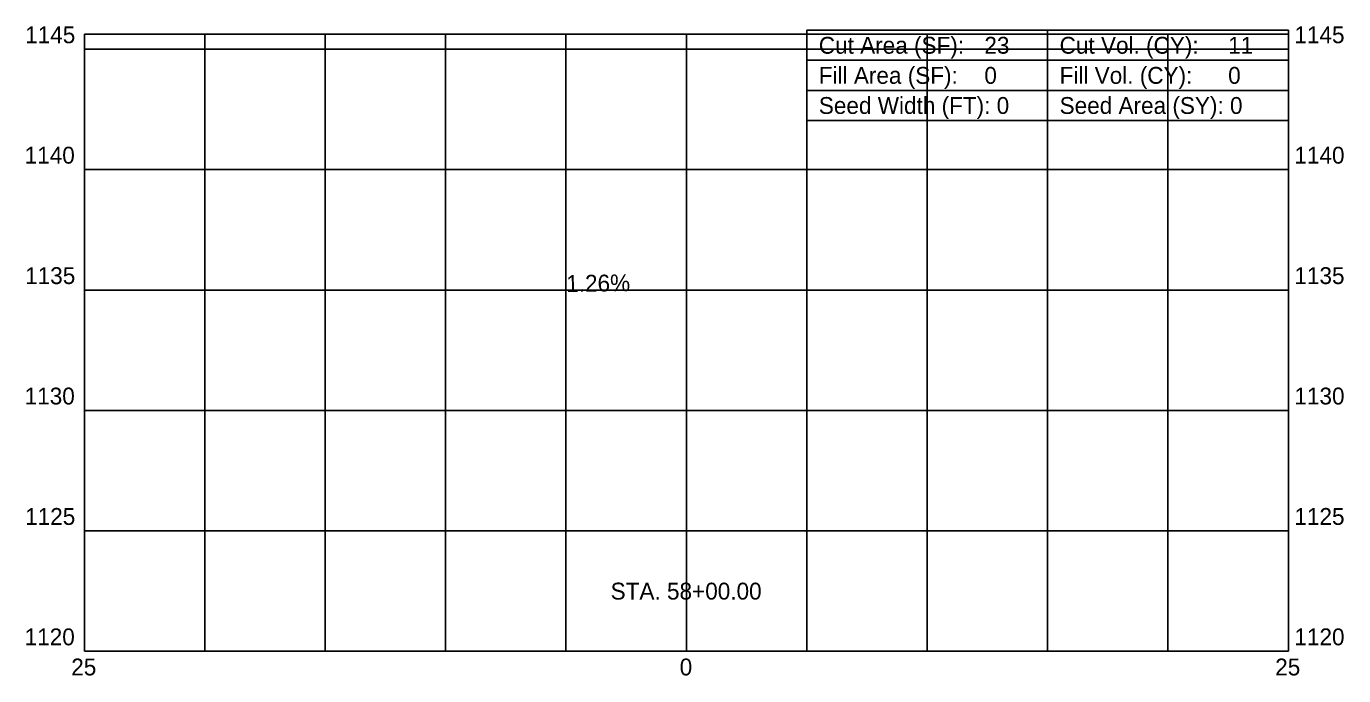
# Model space of a CAD drawing. Extents: x -27.4 to 27.3, y 1119 to 1146.
import ezdxf

# ---------------------------------------------------------------- set-up
doc = ezdxf.new("R2010")
doc.units = 0
for name, color, linetype in [('Default', 7, 'Continuous'), ('SH_Data', 7, 'Continuous'), ('SH_Major_Grid_Line', 7, 'Continuous'), ('SH_Masking', 7, 'Continuous'), ('SH_Text', 7, 'Continuous')]:
    doc.layers.add(name, color=color, linetype=linetype)

msp = doc.modelspace()

# ---------------------------------------------------------------- linework, layer by layer
at = {"layer": 'Default'}
msp.add_circle((25, 1145.789), 0.000417, dxfattribs=at)
msp.add_circle((25, 1145.789), 0.000417, dxfattribs=at)
msp.add_circle((25, 1145.789), 0.000417, dxfattribs=at)
msp.add_circle((25, 1145.789), 0.000417, dxfattribs=at)
msp.add_circle((25, 1145.789), 0.000417, dxfattribs=at)
msp.add_circle((25, 1145.789), 0.000417, dxfattribs=at)
msp.add_circle((25, 1145.789), 0.000417, dxfattribs=at)
msp.add_circle((25, 1145.789), 0.000417, dxfattribs=at)
msp.add_circle((25, 1145.789), 0.000417, dxfattribs=at)
msp.add_circle((25, 1145.789), 0.000417, dxfattribs=at)
msp.add_circle((25, 1145.789), 0.000417, dxfattribs=at)
msp.add_circle((25, 1145.789), 0.000417, dxfattribs=at)
at = {"layer": 'SH_Data'}
for p, q in [((5, 1145.789), (25, 1145.789)), ((5, 1145.789), (5, 1143.289)), ((15, 1145.789), (15, 1142.039)), ((25, 1145.789), (25, 1143.289)), ((5, 1144.539), (25, 1144.539)), ((5, 1143.289), (25, 1143.289)), ((13.298, 1142.664), (13.298, 1142.664)), ((22.946, 1142.664), (22.946, 1142.664))]:
    msp.add_line(p, q, dxfattribs=at)
msp.add_lwpolyline([(5, 1143.289), (5, 1142.039), (25, 1142.039), (25, 1143.289)], dxfattribs=at)
at = {"layer": 'SH_Major_Grid_Line'}
for p, q in [((-25, 1145.626), (25, 1145.626)), ((-25, 1120), (-25, 1145.626)), ((-20, 1120), (-20, 1145.626)), ((-15, 1120), (-15, 1145.626)), ((-10, 1120), (-10, 1145.626)), ((-5, 1120), (-5, 1145.626)), ((0, 1120), (0, 1145.626)), ((5, 1120), (5, 1145.626)), ((10, 1120), (10, 1145.626)), ((15, 1120), (15, 1145.626)), ((20, 1120), (20, 1145.626)), ((25, 1120), (25, 1145.626)), ((-25, 1145), (25, 1145)), ((-25, 1140), (25, 1140)), ((-25, 1135), (25, 1135)), ((-25, 1130), (25, 1130)), ((-25, 1125), (25, 1125)), ((-25, 1120), (25, 1120))]:
    msp.add_line(p, q, dxfattribs=at)
at = {"layer": 'SH_Masking'}
msp.add_lwpolyline([(5, 1145.789), (25, 1145.789), (25, 1142.039), (5, 1142.039)], close=True, dxfattribs=at)

# ---------------------------------------------------------------- texts
at = {"layer": 'SH_Text'}
for s, p in [('1145', (-27.461, 1145.25)), ('1145', (25.25, 1145.25)), ('Cut Area (SF):', (5.5, 1144.814)), ('23', (12.375, 1144.814)), ('Cut Vol. (CY):', (15.5, 1144.814)), ('11', (22.5, 1144.814)), ('Fill Area (SF):', (5.5, 1143.564)), ('0', (12.375, 1143.564)), ('Fill Vol. (CY):', (15.5, 1143.564)), ('0', (22.5, 1143.564)), ('Seed Width (FT): 0', (5.5, 1142.314)), ('Seed Area (SY): 0', (15.5, 1142.314)), ('1140', (-27.482, 1140.25)), ('1140', (25.25, 1140.25)), ('1135', (-27.461, 1135.25)), ('1135', (25.25, 1135.25)), ('1130', (-27.482, 1130.25)), ('1130', (25.25, 1130.25)), ('1125', (-27.461, 1125.25)), ('1125', (25.25, 1125.25)), ('STA. 58+00.00', (-3.146, 1122.15)), ('1120', (-27.482, 1120.25)), ('1120', (25.25, 1120.25)), ('25', (-25.547, 1119)), ('0', (-0.278, 1119)), ('25', (24.453, 1119))]:
    msp.add_text(s, height=0.7, dxfattribs=at).set_placement(p)
msp.add_text('1.26%', height=0.7, rotation=0.7214, dxfattribs=at).set_placement((-4.987, 1134.92))

doc.saveas('drawing.dxf')
